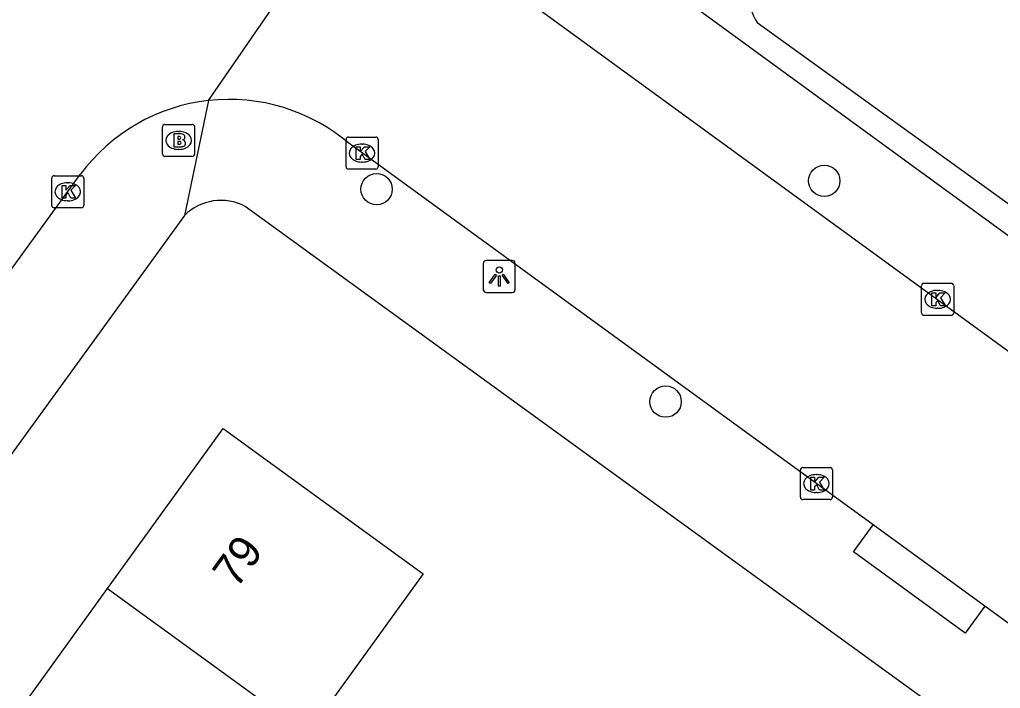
# Model space of a CAD drawing. Extents: x 159675 to 160530, y 382179 to 382901.
# Drawn here: x 160004.31 to 160034.9, y 382438.2 to 382459.06 of the extents above; entities that cross this region are included whole.
import ezdxf

# ---------------------------------------------------------------- set-up
doc = ezdxf.new("R2010")
doc.units = 0
for name, color, linetype in [('IMGEO_Boom', 7, 'Continuous'), ('IMGEO_Brandkraan', 7, 'Continuous'), ('IMGEO_Kolk', 7, 'Continuous'), ('IMGEO_Lichtpunt', 7, 'Continuous'), ('IMGEO_Pand', 7, 'Continuous'), ('IMGEO_Pand_nummerreeks', 7, 'Continuous'), ('IMGEO_Rijbaan_lokaal_open', 7, 'Continuous'), ('IMGEO_Voetpad_open', 7, 'Continuous'), ('IMGEO_Waterloop', 7, 'Continuous')]:
    doc.layers.add(name, color=color, linetype=linetype)

msp = doc.modelspace()

# ---------------------------------------------------------------- linework, layer by layer
at = {"layer": 'IMGEO_Boom'}
for centre in [(160029.407, 382454.029), (160015.443, 382453.768), (160024.457, 382447.144)]:
    msp.add_circle(centre, 0.489, dxfattribs=at)
at = {"layer": 'IMGEO_Brandkraan'}
for p, q in [((160008.842, 382455.789), (160009.694, 382455.789)), ((160008.767, 382454.863), (160008.767, 382455.715)), ((160009.255, 382455.569), (160009.28, 382455.569)), ((160009.768, 382455.715), (160009.768, 382454.863)), ((160009.278, 382455.009), (160009.253, 382455.009)), ((160009.694, 382454.789), (160008.842, 382454.789))]:
    msp.add_line(p, q, dxfattribs=at)
for points in [[(160008.842, 382455.789), (160009.694, 382455.789)], [(160008.767, 382454.863), (160008.767, 382455.715)], [(160009.115, 382455.489), (160009.115, 382455.089), (160009.328, 382455.089)], [(160009.346, 382455.489), (160009.115, 382455.489)], [(160009.768, 382455.715), (160009.768, 382454.863)], [(160009.294, 382455.408), (160009.24, 382455.408), (160009.24, 382455.332)], [(160009.24, 382455.332), (160009.293, 382455.332)], [(160009.302, 382455.256), (160009.24, 382455.256), (160009.24, 382455.175)], [(160009.24, 382455.175), (160009.302, 382455.175)], [(160009.694, 382454.789), (160008.842, 382454.789)]]:
    msp.add_lwpolyline(points, dxfattribs=at)
for centre, radius, start, end in [((160008.844, 382455.713), 0.0765, 91.552, 178.448), ((160008.844, 382455.713), 0.0765, 91.552, 178.448), ((160009.692, 382455.713), 0.0765, 1.552, 88.448), ((160009.692, 382455.713), 0.0765, 1.552, 88.448), ((160009.35, 382455.344), 0.145, 59.4692, 91.5367), ((160009.375, 382455.391), 0.0922, 285.5137, 58.1501), ((160009.295, 382455.37), 0.0379, 267.8285, 90.9355), ((160009.303, 382455.215), 0.0404, 269.8759, 90.5077), ((160009.38, 382455.199), 0.105, 301.3115, 78.989), ((160008.844, 382454.865), 0.0765, 181.552, 268.448), ((160008.844, 382454.865), 0.0765, 181.552, 268.448), ((160009.334, 382455.34), 0.251, 268.6676, 293.5347), ((160009.692, 382454.865), 0.0765, 271.552, 358.448), ((160009.692, 382454.865), 0.0765, 271.552, 358.448)]:
    msp.add_arc(centre, radius, start, end, dxfattribs=at)
for centre, major_axis, ratio, start_param, end_param in [((160009.254, 382455.289), (-0.387, 0.002), 0.722429, 4.712389, 7.853982), ((160009.279, 382455.289), (-0.39, 0.002), 0.717154, 1.570796, 4.712389)]:
    msp.add_ellipse(centre, major_axis=major_axis, ratio=ratio, start_param=start_param, end_param=end_param, dxfattribs=at)
at = {"layer": 'IMGEO_Kolk'}
for p, q in [((160014.49, 382454.467), (160014.49, 382455.319)), ((160014.565, 382455.393), (160015.417, 382455.393)), ((160014.978, 382455.173), (160015.003, 382455.173)), ((160015.491, 382455.319), (160015.491, 382454.467)), ((160015.001, 382454.613), (160014.976, 382454.613)), ((160015.417, 382454.393), (160014.565, 382454.393)), ((160005.31, 382453.261), (160005.31, 382454.113)), ((160005.385, 382454.187), (160006.237, 382454.187)), ((160005.798, 382453.967), (160005.823, 382453.967)), ((160006.311, 382454.113), (160006.311, 382453.261)), ((160005.821, 382453.407), (160005.796, 382453.407)), ((160006.237, 382453.187), (160005.385, 382453.187)), ((160032.443, 382449.907), (160032.443, 382450.759)), ((160032.518, 382450.833), (160033.37, 382450.833)), ((160032.931, 382450.613), (160032.956, 382450.613)), ((160033.444, 382450.759), (160033.444, 382449.907)), ((160032.954, 382450.053), (160032.929, 382450.053)), ((160033.37, 382449.833), (160032.518, 382449.833)), ((160028.738, 382445.087), (160029.59, 382445.087)), ((160028.663, 382444.161), (160028.663, 382445.013)), ((160029.151, 382444.867), (160029.176, 382444.867)), ((160029.664, 382445.013), (160029.664, 382444.161)), ((160029.174, 382444.307), (160029.149, 382444.307)), ((160029.59, 382444.087), (160028.738, 382444.087))]:
    msp.add_line(p, q, dxfattribs=at)
for points in [[(160014.49, 382454.467), (160014.49, 382455.319)], [(160014.565, 382455.393), (160015.417, 382455.393)], [(160015.491, 382455.319), (160015.491, 382454.467)], [(160014.811, 382455.093), (160014.934, 382455.093), (160014.934, 382454.942), (160015.064, 382455.093), (160015.228, 382455.093), (160015.082, 382454.942), (160015.235, 382454.693), (160015.083, 382454.693), (160014.998, 382454.857), (160014.934, 382454.79), (160014.934, 382454.693), (160014.811, 382454.693), (160014.811, 382455.093)], [(160015.417, 382454.393), (160014.565, 382454.393)], [(160005.31, 382453.261), (160005.31, 382454.113)], [(160005.385, 382454.187), (160006.237, 382454.187)], [(160006.311, 382454.113), (160006.311, 382453.261)], [(160005.631, 382453.887), (160005.754, 382453.887), (160005.754, 382453.736), (160005.884, 382453.887), (160006.048, 382453.887), (160005.902, 382453.736), (160006.055, 382453.487), (160005.903, 382453.487), (160005.818, 382453.651), (160005.754, 382453.584), (160005.754, 382453.487), (160005.631, 382453.487), (160005.631, 382453.887)], [(160006.237, 382453.187), (160005.385, 382453.187)], [(160032.443, 382449.907), (160032.443, 382450.759)], [(160032.518, 382450.833), (160033.37, 382450.833)], [(160032.764, 382450.533), (160032.887, 382450.533), (160032.887, 382450.382), (160033.017, 382450.533), (160033.181, 382450.533), (160033.035, 382450.382), (160033.188, 382450.133), (160033.036, 382450.133), (160032.951, 382450.297), (160032.887, 382450.23), (160032.887, 382450.133), (160032.764, 382450.133), (160032.764, 382450.533)], [(160033.444, 382450.759), (160033.444, 382449.907)], [(160033.37, 382449.833), (160032.518, 382449.833)], [(160028.738, 382445.087), (160029.59, 382445.087)], [(160028.663, 382444.161), (160028.663, 382445.013)], [(160028.984, 382444.787), (160029.107, 382444.787), (160029.107, 382444.636), (160029.237, 382444.787), (160029.401, 382444.787), (160029.255, 382444.636), (160029.408, 382444.387), (160029.256, 382444.387), (160029.171, 382444.551), (160029.107, 382444.484), (160029.107, 382444.387), (160028.984, 382444.387), (160028.984, 382444.787)], [(160029.664, 382445.013), (160029.664, 382444.161)], [(160029.59, 382444.087), (160028.738, 382444.087)]]:
    msp.add_lwpolyline(points, dxfattribs=at)
for centre, start, end in [((160014.567, 382455.317), 91.552, 178.448), ((160014.567, 382455.317), 91.552, 178.448), ((160015.415, 382455.317), 1.552, 88.448), ((160015.415, 382455.317), 1.552, 88.448), ((160014.567, 382454.469), 181.552, 268.448), ((160014.567, 382454.469), 181.552, 268.448), ((160015.415, 382454.469), 271.552, 358.448), ((160015.415, 382454.469), 271.552, 358.448), ((160005.387, 382454.111), 91.552, 178.448), ((160005.387, 382454.111), 91.552, 178.448), ((160006.235, 382454.111), 1.552, 88.448), ((160006.235, 382454.111), 1.552, 88.448), ((160005.387, 382453.263), 181.552, 268.448), ((160005.387, 382453.263), 181.552, 268.448), ((160006.235, 382453.263), 271.552, 358.448), ((160006.235, 382453.263), 271.552, 358.448), ((160032.52, 382450.757), 91.552, 178.448), ((160032.52, 382450.757), 91.552, 178.448), ((160033.368, 382450.757), 1.552, 88.448), ((160033.368, 382450.757), 1.552, 88.448), ((160032.52, 382449.909), 181.552, 268.448), ((160032.52, 382449.909), 181.552, 268.448), ((160033.368, 382449.909), 271.552, 358.448), ((160033.368, 382449.909), 271.552, 358.448), ((160028.74, 382445.011), 91.552, 178.448), ((160028.74, 382445.011), 91.552, 178.448), ((160029.588, 382445.011), 1.552, 88.448), ((160029.588, 382445.011), 1.552, 88.448), ((160028.74, 382444.163), 181.552, 268.448), ((160028.74, 382444.163), 181.552, 268.448), ((160029.588, 382444.163), 271.552, 358.448), ((160029.588, 382444.163), 271.552, 358.448)]:
    msp.add_arc(centre, 0.0765, start, end, dxfattribs=at)
for centre, major_axis, ratio, start_param, end_param in [((160014.977, 382454.893), (-0.387, 0.002), 0.722429, 4.712389, 7.853982), ((160015.002, 382454.893), (-0.39, 0.002), 0.717154, 1.570796, 4.712389), ((160005.797, 382453.687), (-0.387, 0.002), 0.722429, 4.712389, 7.853982), ((160005.822, 382453.687), (-0.39, 0.002), 0.717154, 1.570796, 4.712389), ((160032.93, 382450.333), (-0.387, 0.002), 0.722429, 4.712389, 7.853982), ((160032.955, 382450.333), (-0.39, 0.002), 0.717154, 1.570796, 4.712389), ((160029.15, 382444.587), (-0.387, 0.002), 0.722429, 4.712389, 7.853982), ((160029.175, 382444.587), (-0.39, 0.002), 0.717154, 1.570796, 4.712389)]:
    msp.add_ellipse(centre, major_axis=major_axis, ratio=ratio, start_param=start_param, end_param=end_param, dxfattribs=at)
at = {"layer": 'IMGEO_Lichtpunt'}
for p, q in [((160018.771, 382451.451), (160018.771, 382450.644)), ((160018.771, 382451.451), (160018.771, 382450.644)), ((160019.673, 382451.546), (160018.865, 382451.546)), ((160019.673, 382451.546), (160018.865, 382451.546)), ((160019.767, 382450.644), (160019.767, 382451.451)), ((160019.767, 382450.644), (160019.767, 382451.451)), ((160018.865, 382450.55), (160019.673, 382450.55)), ((160018.865, 382450.55), (160019.673, 382450.55))]:
    msp.add_line(p, q, dxfattribs=at)
for points in [[(160019.145, 382451.115), (160019.184, 382451.087), (160018.996, 382450.825), (160018.958, 382450.852), (160019.145, 382451.115)], [(160019.247, 382451.067), (160019.294, 382451.067), (160019.294, 382450.745), (160019.247, 382450.745), (160019.247, 382451.067)], [(160019.357, 382451.087), (160019.395, 382451.114), (160019.582, 382450.852), (160019.543, 382450.824), (160019.357, 382451.087)]]:
    msp.add_lwpolyline(points, dxfattribs=at)
msp.add_circle((160019.27, 382451.249), 0.0994, dxfattribs=at)
for centre, start, end in [((160018.865, 382451.451), 90, 180), ((160018.865, 382451.451), 90, 180), ((160019.673, 382451.451), 0, 90), ((160019.673, 382451.451), 0, 90), ((160018.865, 382450.644), 180, 270), ((160018.865, 382450.644), 180, 270), ((160019.673, 382450.644), 270, 0), ((160019.673, 382450.644), 270, 360)]:
    msp.add_arc(centre, 0.0946, start, end, dxfattribs=at)
at = {"layer": 'IMGEO_Pand'}
for points in [[(160007.045, 382441.312), (160010.66, 382446.304), (160016.9, 382441.774), (160013.288, 382436.787)], [(160003.542, 382436.474), (160007.045, 382441.312)], [(160007.045, 382441.312), (160013.288, 382436.787)]]:
    msp.add_lwpolyline(points, dxfattribs=at)
at = {"layer": 'IMGEO_Rijbaan_lokaal_open'}
for points in [[(160010.202, 382456.532), (160015.978, 382464.923)], [(160018.366, 382460.946), (160123.455, 382384.426)], [(160030.935, 382443.3), (160014.616, 382455.167)], [(159984.695, 382424.782), (159986.94, 382427.882), (159990.318, 382432.531), (160000, 382445.699), (160006.199, 382454.224)], [(160034.415, 382440.769), (160030.935, 382443.3)], [(160099.29, 382393.592), (160034.415, 382440.769)]]:
    msp.add_lwpolyline(points, dxfattribs=at)
for centre, radius, start, end in [((160010.844, 382450.793), 5.775, 96.3858, 143.5469), ((160010.844, 382450.79), 5.778, 49.25, 96.3822)]:
    msp.add_arc(centre, radius, start, end, dxfattribs=at)
at = {"layer": 'IMGEO_Voetpad_open'}
for points in [[(160043.937, 382454.91), (160041.474, 382451.508), (160039.671, 382449.018), (160025.191, 382459.567)], [(160010.202, 382456.532), (160009.446, 382452.95)], [(160033.01, 382437.511), (160011.345, 382453.23)], [(160009.446, 382452.95), (160000, 382439.936), (159979.481, 382411.665)], [(160034.415, 382440.769), (160033.804, 382439.927), (160030.324, 382442.458), (160030.935, 382443.3)]]:
    msp.add_lwpolyline(points, dxfattribs=at)
msp.add_arc((160010.588, 382451.786), 1.631, 62.3352, 134.44, dxfattribs=at)
at = {"layer": 'IMGEO_Waterloop'}
msp.add_lwpolyline([(160027.312, 382458.967), (160038.018, 382451.248)], dxfattribs=at)
msp.add_arc((160029.276, 382460.152), 2.294, 119.8003, 211.102, dxfattribs=at)

# ---------------------------------------------------------------- texts
at = {"layer": 'IMGEO_Pand_nummerreeks'}
msp.add_text('79', height=1, rotation=54.0922, dxfattribs=at).set_placement((160011.072, 382441.28))

doc.saveas('drawing.dxf')
